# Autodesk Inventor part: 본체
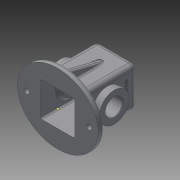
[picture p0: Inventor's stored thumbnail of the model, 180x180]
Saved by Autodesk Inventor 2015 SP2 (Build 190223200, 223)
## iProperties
Created: 2017-07
Part Number: 본체
Material: 일반
Document SubType Name: Modeling
Designer: Admin
Density: 1 g/cm^3
Appearance: 기본값
Author: Admin
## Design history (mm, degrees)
sketch "스케치1"
  geometry: L1 (75, 0)-(-75, 0); L2 (0, 0)-(0, -65); 2 further points; 1 other entity
  constraints: 4 end point, 2 coincident, 2 horizontal, 1 midpoint, 1 vertical, 4 other
  dimensions: "d1" = 150 distance of L1.start L1.end; "d2" = 65 distance of L2.start L2.end
extrude "돌출1" new body sketch "스케치1" distance "d3" = 10; taper "d4" = 0 deg
sketch "스케치2"
  geometry: L1 (-37, -37)-(37, -37); L2 (37, -37)-(37, 37); L3 (37, 37)-(-37, 37); L4 (-37, 37)-(-37, -37); L5 (-37, -37)-(37, 37); L6 (37, -37)-(-37, 37); 1 further point
  constraints: 12 end point, 2 midpoint, 2 parallel, 1 horizontal, 1 perpendicular
  dimensions: "d5" = 74 distance of L3.end L2.end; "d6" = 74 distance of L2.end L1.end
extrude "돌출2" join sketch "스케치2" distance "d7" = 100; taper "d8" = 0 deg
sketch "스케치3"
  geometry: L1 (-32, 0)-(32, 0); L2 (37, 110)-(-37, 110) reference; L3 (32, 105)-(-32, 105); L4 (0, 55)-(-32, 55); L5 (-32, 55)-(-32, 82.5); L6 (-37, 10)-(-37, 110) reference; L7 (-25, 55)-(-25, 75.5); L8 (-32, 82.5)-(-25, 75.5); L9 (25, 55)-(25, 75.5); L10 (32, 82.5)-(25, 75.5); L11 (0, 55)-(32, 55); L12 (-25, 55)-(-32, 55); L13 (25, 55)-(32, 55); L14 (-32, 55)-(-32, 82.5); L15 (-32, 82.5)-(-25, 75.5); L16 (-25, 55)-(-25, 75.5); L17 (25, 55)-(25, 75.5); L18 (25, 75.5)-(32, 82.5); L19 (32, 82.5)-(32, 55); L20 (-32, 55)-(-32, 82.5); L21 (-32, 82.5)-(-25, 75.5); L22 (-32, 55)-(-25, 55); L23 (32, 55)-(25, 55); L24 (25, 55)-(25, 75.5); L25 (25, 75.5)-(32, 82.5); L26 (32, 82.5)-(32, 55); L27 (-25, 55)-(25, 55); L28 (-32, 55)-(32, 55); L29 (-32, 82.5)-(-32, 105); L30 (32, 82.5)-(32, 105); L31 (-32, 55)-(-32, 0); L32 (32, 55)-(32, 0); L33 (-32, 55)-(-25, 55); L34 (-25, 55)-(-25, 75.5); L35 (-25, 75.5)-(-32, 82.5); L36 (-32, 82.5)-(-32, 55); L37 (32, 55)-(25, 55); L38 (25, 55)-(25, 75.5); L39 (25, 75.5)-(32, 82.5); 1 further point
  constraints: 74 end point, 7 horizontal, 7 perpendicular, 5 vertical, 4 parallel, 3 collinear, 2 point on line
  dimensions: "d10" = 5 distance between parallel lines of L2 L3; "d12" = 27.5 distance of L4.end L5.end; "d17" = 55 distance between parallel lines of L4 L2; "d20" = 15.9099 distance from line of L2.start L10; "d21" = 27.5 distance from line of L10.start L2; "d23" = 37 distance from line of L4.start L6; "d24" = 135 deg angle of L6 L8; "d27" = 90 deg angle of L26 L2; "d28" = 110 distance between parallel lines of L1 L2; "d29" = 62 distance between parallel lines of L38 L6; "d30" = 12 distance between parallel lines of L34 L6; "d31" = 5 distance between parallel lines of L31 L6
extrude "돌출3" cut sketch "스케치3" stored distance "d25" = 64; taper "d26" = 0 deg
sketch "스케치4"
  geometry: L1 (0, 0)-(0, 55); L2 (0, 55)-(-50, 55); L3 (-50, 55)-(-50, 82.5); L4 (-37, 10)-(-37, 110) reference; L5 (-32, 0)-(-32, 105) reference; L6 (-50, 82.5)-(-32, 82.5); L7 (-32, 82.5)-(-25, 75.5); L8 (-25, 55)-(-25, 75.5); L9 (-50, 55)-(-50, 71); L10 (-50, 71)-(-25, 71)
  constraints: 16 end point, 3 point on line, 2 perpendicular, 2 vertical, 1 horizontal, 1 midpoint, 1 parallel
  dimensions: "d32" = 55 distance of L1.start L1.end; "d33" = 50 distance of L1.end L2.end; "d34" = 27.5 distance of L2.end L3.end; "d35" = 135 deg angle of L4 L7; "d36" = 7 distance between parallel lines of L5 L8; "d37" = 16 distance of L2.end L9.end
revolve "회전1" stored, may be unused: angle "d38" = 90 deg
revolve "회전2" stored, may be unused: angle "d39" = 90 deg
sketch "스케치5"
  geometry: L1 (-20, 110)-(20, 110); L2 (37, 110)-(-37, 110) reference; L3 (-20, 110)-(-19.125, 120); L4 (20, 110)-(19.125, 120); L5 (-37, 10)-(-37, 110) reference; L6 (37, 10)-(37, 110) reference; L7 (-19.125, 120)-(19.125, 120); 2 further points
  constraints: 8 end point, 2 midpoint, 1 horizontal
  dimensions: "d40" = 40 distance of L1.start L1.end; "d41" = 5 deg angle of L3 L5; "d42" = 5 deg angle of L4 L6; "d43" = 10 distance between parallel lines of L2 L7
extrude "돌출4" join sketch "스케치5" stored distance "d44" = 40; taper "d45" = 0 deg
sketch "스케치6"
  geometry: L1 (10, 37)-(110, 37) reference; L2 (110, -37)-(110, 37) reference; L3 (120, 20)-(110, 20) reference; L4 (110, 20)-(120, 19.125); L5 (110, -20)-(120, -20) reference; L6 (110, -20)-(120, -19.125); L7 (10, -37)-(110, -37) reference; L8 (120, -20)-(120, 20) reference; 1 further point
  constraints: 4 end point, 2 point on line
  dimensions: "d46" = 5 deg angle of L4 L1; "d47" = 5 deg angle of L6 L7
extrude "돌출5" cut sketch "스케치6" stored distance "d48" = 40; taper "d49" = 0 deg
sketch "스케치7"
  geometry: L1 (0, 0)-(0, 22.5); C1 r 27.5 at (0, 0) reference; 2 further points
  constraints: 2 end point, 1 coincident, 1 vertical
  dimensions: "d50" = 22.5 distance of L1.start L1.end
hole "구멍1" sketch "스케치7" at (0, 22.5) diameter "d51" = 3.242; stored, may be unused: countersink angle "d55" = 90 deg, drill point angle "d57" = 118 deg; dims "d52" = 8, "d53" = 4, "d54" = 2, "d56" = 10
sketch "스케치8"
  geometry: 2 further points
  constraints: 1 coincident
hole "구멍2" sketch "스케치8" at (19.125, 19.125) diameter "d61" = 21; stored, may be unused: countersink angle "d65" = 90 deg, drill point angle "d67" = 0 deg; dims "d62" = 8, "d63" = 28, "d64" = 4, "d66" = 30
sketch "스케치9"
  geometry: L1 (-58, 0)-(58, 0); 4 further points
  constraints: 3 coincident, 2 end point, 1 horizontal, 1 midpoint
  dimensions: "d68" = 116 distance of L1.start L1.end
hole "구멍3" sketch "스케치9" at (-58, 0), (58, 0) diameter "d69" = 10; stored, may be unused: countersink angle "d73" = 90 deg, drill point angle "d75" = 0 deg; dims "d70" = 8, "d71" = 28, "d72" = 4, "d74" = 30
sketch "스케치10"
  geometry: L1 (10, 55)-(85.176, 36.256)
  constraints: 2 end point
  dimensions: "d86" = 75.1765 horizontal distance of L1.start L1.end
feature "리브1" sketch "스케치10" dims "d94" = 1, "d95" = 10, "d96" = 0, "d97" = 0, "d98" = 1, "d99" = 1
fillet "모깎기1" dims "d100" = 0.5, "d101" = 3, "d102" = 8
chamfer "모따기1" distance "d103" = 1; stored, may be unused: second distance "d104" = 2, angle "d105" = 45 deg
sketch "스케치11"
  geometry: L1 (-12.863, 107)-(-45.137, 107) reference; L2 (-29, 107)-(-29, 77); 2 further points
  constraints: 2 end point, 1 coincident, 1 midpoint, 1 vertical, 1 other
  dimensions: "d106" = 30 distance of L2.start L2.end
feature "엠보싱1" sketch "스케치11" dims "d1" = 150, "d2" = 65, "d12" = 27.5, "d107" = 0.5, "d108" = 0
sketch "스케치12"
  geometry: 1 further point
node "솔리드1"
mirror "대칭1"
pattern_circular "원형 패턴1" dims angle "d59" = 360 deg
mirror "대칭2"
mirror "대칭3"
